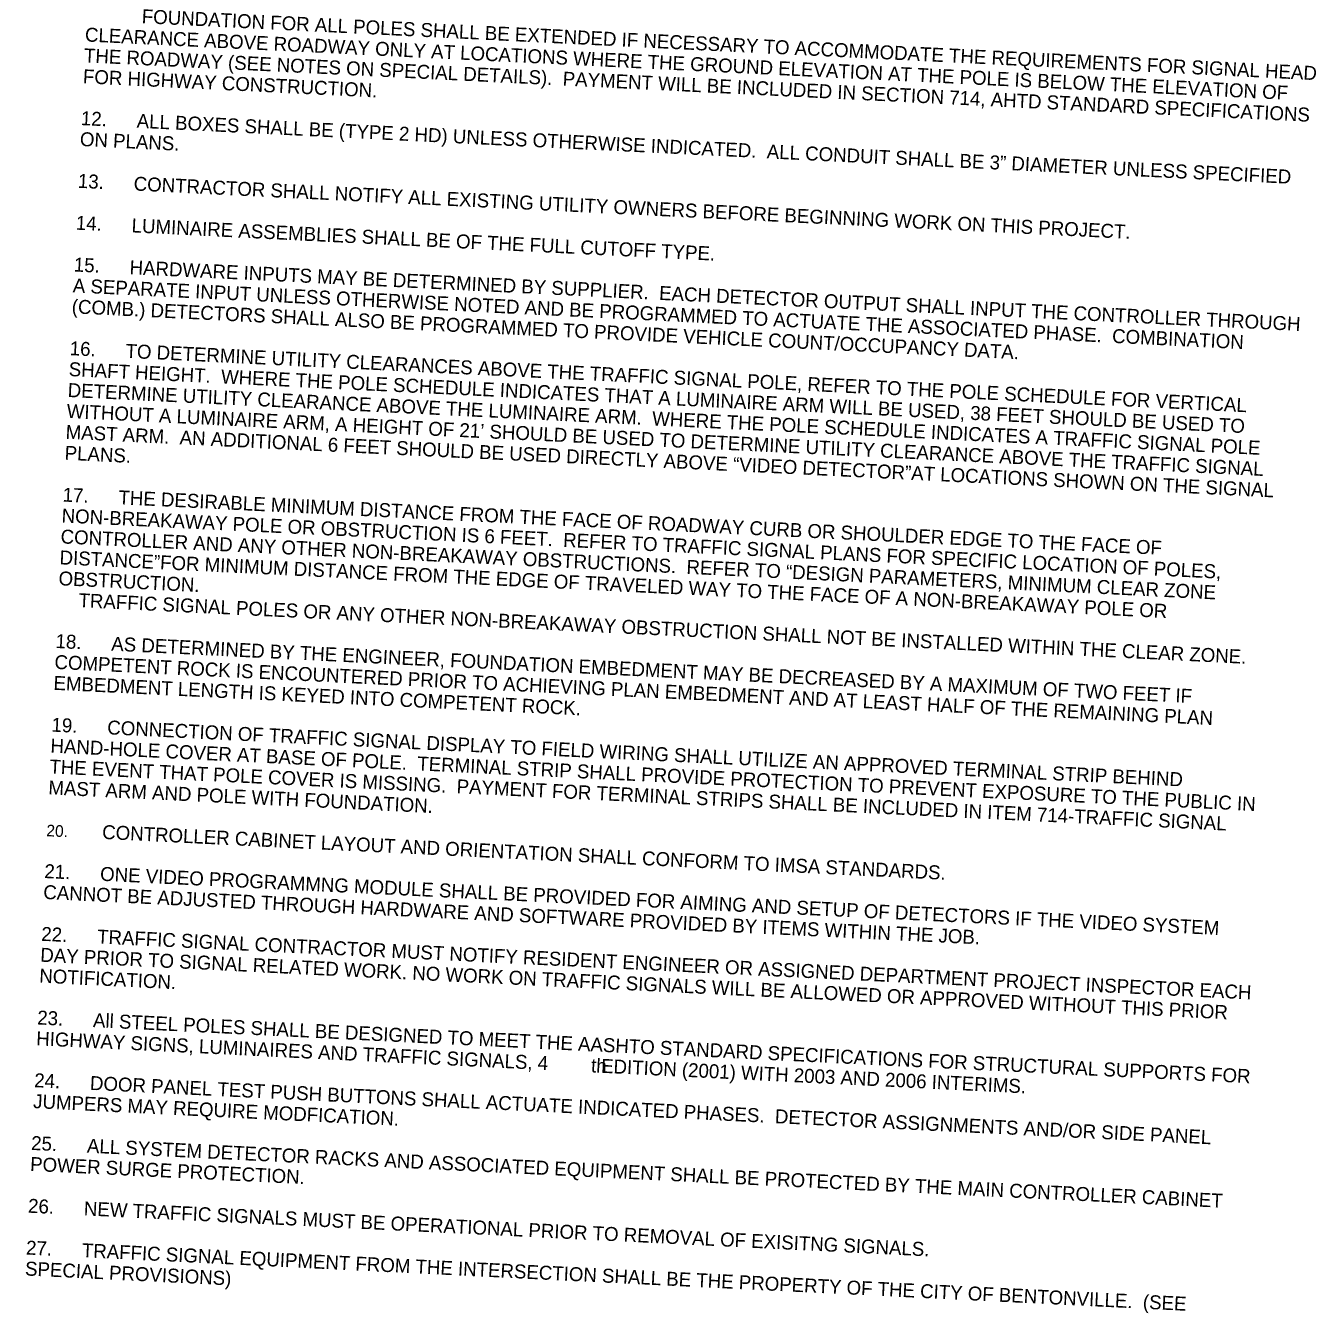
# Model space of a CAD drawing. Extents: x 669100 to 670534, y 743337 to 744379.
# Drawn here: x 669138.1 to 669369.1, y 743369.2 to 743599.8 of the extents above; entities that cross this region are included whole.
import ezdxf

# ---------------------------------------------------------------- set-up
doc = ezdxf.new("R2010")
doc.units = 0
doc.layers.add('R_Proposed Road Annot', color=7, linetype='Continuous')

msp = doc.modelspace()

# ---------------------------------------------------------------- texts
at = {"layer": 'R_Proposed Road Annot'}
for s, height, p in [('FOUNDATION FOR ALL POLES SHALL BE EXTENDED IF NECESSARY TO ACCOMMODATE THE REQUIREMENTS FOR SIGNAL HEAD ', 2.5, (669158.79, 743600.26)), ('CLEARANCE ABOVE ROADWAY ONLY AT LOCATIONS WHERE THE GROUND ELEVATION AT THE POLE IS BELOW THE ELEVATION OF ', 2.5, (669148.62, 743596.99)), ('THE ROADWAY (SEE NOTES ON SPECIAL DETAILS).  PAYMENT WILL BE INCLUDED IN SECTION 714, AHTD STANDARD SPECIFICATIONS ', 2.5, (669148.44, 743593.25)), ('FOR HIGHWAY CONSTRUCTION.', 2.5, (669148.26, 743589.5)), ('12.', 2.5, (669147.89, 743582.01)), ('ALL BOXES SHALL BE (TYPE 2 HD) UNLESS OTHERWISE INDICATED.  ALL CONDUIT SHALL BE 3” DIAMETER UNLESS SPECIFIED ', 2.5, (669157.88, 743581.53)), ('ON PLANS.  ', 2.5, (669147.71, 743578.27)), ('13.', 2.5, (669147.35, 743570.78)), ('CONTRACTOR SHALL NOTIFY ALL EXISTING UTILITY OWNERS BEFORE BEGINNING WORK ON THIS PROJECT.', 2.5, (669157.34, 743570.29)), ('14.', 2.5, (669146.98, 743563.28)), ('LUMINAIRE ASSEMBLIES SHALL BE OF THE FULL CUTOFF TYPE.', 2.5, (669156.97, 743562.8)), ('15.', 2.5, (669146.62, 743555.79)), ('HARDWARE INPUTS MAY BE DETERMINED BY SUPPLIER.  EACH DETECTOR OUTPUT SHALL INPUT THE CONTROLLER THROUGH ', 2.5, (669156.61, 743555.31)), ('A SEPARATE INPUT UNLESS OTHERWISE NOTED AND BE PROGRAMMED TO ACTUATE THE ASSOCIATED PHASE.  COMBINATION ', 2.5, (669146.44, 743552.05)), ('(COMB.) DETECTORS SHALL ALSO BE PROGRAMMED TO PROVIDE VEHICLE COUNT/OCCUPANCY DATA.', 2.5, (669146.26, 743548.3)), ('16.', 2.5, (669145.89, 743540.81)), ('TO DETERMINE UTILITY CLEARANCES ABOVE THE TRAFFIC SIGNAL POLE, REFER TO THE POLE SCHEDULE FOR VERTICAL ', 2.5, (669155.88, 743540.33)), ('SHAFT HEIGHT.  WHERE THE POLE SCHEDULE INDICATES THAT A LUMINAIRE ARM WILL BE USED, 38 FEET SHOULD BE USED TO ', 2.5, (669145.71, 743537.07)), ('DETERMINE UTILITY CLEARANCE ABOVE THE LUMINAIRE ARM.  WHERE THE POLE SCHEDULE INDICATES A TRAFFIC SIGNAL POLE ', 2.5, (669145.53, 743533.32)), ('WITHOUT A LUMINAIRE ARM, A HEIGHT OF 21’ SHOULD BE USED TO DETERMINE UTILITY CLEARANCE ABOVE THE TRAFFIC SIGNAL ', 2.5, (669145.35, 743529.57)), ('MAST ARM.  AN ADDITIONAL 6 FEET SHOULD BE USED DIRECTLY ABOVE “VIDEO DETECTOR”AT LOCATIONS SHOWN ON THE SIGNAL ', 2.5, (669145.16, 743525.83)), ('PLANS.  ', 2.5, (669144.98, 743522.08)), ('17.', 2.5, (669144.62, 743514.59)), ('THE DESIRABLE MINIMUM DISTANCE FROM THE FACE OF ROADWAY CURB OR SHOULDER EDGE TO THE FACE OF ', 2.5, (669154.61, 743514.11)), ('NON-BREAKAWAY POLE OR OBSTRUCTION IS 6 FEET.  REFER TO TRAFFIC SIGNAL PLANS FOR SPECIFIC LOCATION OF POLES, ', 2.5, (669144.44, 743510.85)), ('CONTROLLER AND ANY OTHER NON-BREAKAWAY OBSTRUCTIONS.  REFER TO “DESIGN PARAMETERS, MINIMUM CLEAR ZONE ', 2.5, (669144.26, 743507.1)), ('DISTANCE”FOR MINIMUM DISTANCE FROM THE EDGE OF TRAVELED WAY TO THE FACE OF A NON-BREAKAWAY POLE OR ', 2.5, (669144.07, 743503.35)), ('OBSTRUCTION.', 2.5, (669143.89, 743499.61)), ('TRAFFIC SIGNAL POLES OR ANY OTHER NON-BREAKAWAY OBSTRUCTION SHALL NOT BE INSTALLED WITHIN THE CLEAR ZONE.', 2.5, (669147.46, 743495.68)), ('18.', 2.5, (669143.35, 743488.37)), ('AS DETERMINED BY THE ENGINEER, FOUNDATION EMBEDMENT MAY BE DECREASED BY A MAXIMUM OF TWO FEET IF ', 2.5, (669153.33, 743487.89)), ('COMPETENT ROCK IS ENCOUNTERED PRIOR TO ACHIEVING PLAN EMBEDMENT AND AT LEAST HALF OF THE REMAINING PLAN ', 2.5, (669143.16, 743484.63)), ('EMBEDMENT LENGTH IS KEYED INTO COMPETENT ROCK.  ', 2.5, (669142.98, 743480.88)), ('19.', 2.5, (669142.62, 743473.39)), ('CONNECTION OF TRAFFIC SIGNAL DISPLAY TO FIELD WIRING SHALL UTILIZE AN APPROVED TERMINAL STRIP BEHIND ', 2.5, (669152.61, 743472.91)), ('HAND-HOLE COVER AT BASE OF POLE.  TERMINAL STRIP SHALL PROVIDE PROTECTION TO PREVENT EXPOSURE TO THE PUBLIC IN ', 2.5, (669142.44, 743469.64)), ('THE EVENT THAT POLE COVER IS MISSING.  PAYMENT FOR TERMINAL STRIPS SHALL BE INCLUDED IN ITEM 714-TRAFFIC SIGNAL ', 2.5, (669142.25, 743465.9)), ('MAST ARM AND POLE WITH FOUNDATION.', 2.5, (669142.07, 743462.15)), ('20.', 2.083, (669141.71, 743454.66)), ('CONTROLLER CABINET LAYOUT AND ORIENTATION SHALL CONFORM TO IMSA STANDARDS.', 2.5, (669151.7, 743454.18)), ('21.', 2.5, (669141.35, 743447.17)), ('ONE VIDEO PROGRAMMNG MODULE SHALL BE PROVIDED FOR AIMING AND SETUP OF DETECTORS IF THE VIDEO SYSTEM ', 2.5, (669151.33, 743446.69)), ('CANNOT BE ADJUSTED THROUGH HARDWARE AND SOFTWARE PROVIDED BY ITEMS WITHIN THE JOB.', 2.5, (669141.16, 743443.43)), ('22.', 2.5, (669140.8, 743435.93)), ('TRAFFIC SIGNAL CONTRACTOR MUST NOTIFY RESIDENT ENGINEER OR ASSIGNED DEPARTMENT PROJECT INSPECTOR EACH ', 2.5, (669150.79, 743435.45)), ('DAY PRIOR TO SIGNAL RELATED WORK. NO WORK ON TRAFFIC SIGNALS WILL BE ALLOWED OR APPROVED WITHOUT THIS PRIOR ', 2.5, (669140.62, 743432.19)), ('NOTIFICATION.', 2.5, (669140.44, 743428.44)), ('23.', 2.5, (669140.07, 743420.95)), ('All STEEL POLES SHALL BE DESIGNED TO MEET THE AASHTO STANDARD SPECIFICATIONS FOR STRUCTURAL SUPPORTS FOR ', 2.5, (669150.06, 743420.47)), ('HIGHWAY SIGNS, LUMINAIRES AND TRAFFIC SIGNALS, 4', 2.5, (669139.89, 743417.21)), ('th', 2.5, (669239.24, 743412.38)), (' EDITION (2001) WITH 2003 AND 2006 INTERIMS.', 2.5, (669240.1, 743412.34)), ('24.', 2.5, (669139.53, 743409.72)), ('DOOR PANEL TEST PUSH BUTTONS SHALL ACTUATE INDICATED PHASES.  DETECTOR ASSIGNMENTS AND/OR SIDE PANEL ', 2.5, (669149.51, 743409.23)), ('JUMPERS MAY REQUIRE MODFICATION.', 2.5, (669139.34, 743405.97)), ('25.', 2.5, (669138.98, 743398.48)), ('ALL SYSTEM DETECTOR RACKS AND ASSOCIATED EQUIPMENT SHALL BE PROTECTED BY THE MAIN CONTROLLER CABINET ', 2.5, (669148.97, 743397.99)), ('POWER SURGE PROTECTION.', 2.5, (669138.8, 743394.73)), ('26.', 2.5, (669138.43, 743387.24)), ('NEW TRAFFIC SIGNALS MUST BE OPERATIONAL PRIOR TO REMOVAL OF EXISITNG SIGNALS.', 2.5, (669148.42, 743386.76)), ('27.', 2.5, (669138.07, 743379.75)), ('TRAFFIC SIGNAL EQUIPMENT FROM THE INTERSECTION SHALL BE THE PROPERTY OF THE CITY OF BENTONVILLE.  (SEE ', 2.5, (669148.06, 743379.27)), ('SPECIAL PROVISIONS)', 2.5, (669137.89, 743376))]:
    msp.add_text(s, height=height, rotation=357.2199, dxfattribs=at).set_placement(p)

doc.saveas('drawing.dxf')
